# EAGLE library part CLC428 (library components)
Dual wideband Op Amp
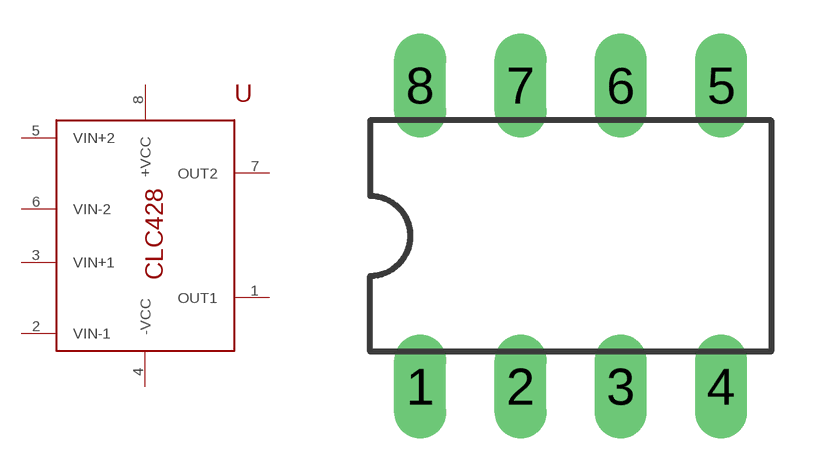
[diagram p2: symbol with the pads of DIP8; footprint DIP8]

Designator prefix -

## CLC428  [DIP8]
1  OUT1
2  VIN-1
3  VIN+1
4  -VCC
5  VIN+2
6  VIN-2
7  OUT2
8  +VCC

## Footprint DIP8 (pad centres in mm)
drill 0.813 long: 1 -3.81,-3.81; 2 -1.27,-3.81; 3 1.27,-3.81; 4 3.81,-3.81; 5 3.81,3.81; 6 1.27,3.81; 7 -1.27,3.81; 8 -3.81,3.81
